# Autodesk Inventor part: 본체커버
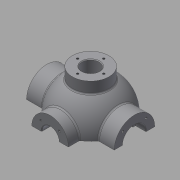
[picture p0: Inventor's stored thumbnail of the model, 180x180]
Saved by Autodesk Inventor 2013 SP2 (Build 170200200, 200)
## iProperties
Created: 2015-12
Part Number: 본체커버
Material: 일반
Document SubType Name: Modeling
Designer: mduedu
Density: 1 g/cm^3
Mass: 574.351 g
Surface Area: 450.515 cm^2
Volume: 211.938 cm^3
Author: mduedu
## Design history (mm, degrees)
sketch "스케치1"
  geometry: L1 (-53, 0)-(53, 0); A1 r 53 centre (0, 0) between (53, 0) and (-53, 0); 2 further points
  constraints: 2 coincident, 2 end point, 2 point on circle, 1 centre point, 1 horizontal, 1 midpoint
  dimensions: "d0" = 53 radius of A1
revolve "회전1" sketch "스케치1" stored, may be unused: angle "d2" = 90 deg
feature "쉘1" dims "d11" = 10
node "작업 평면1"
sketch "스케치2"
  geometry: C1 r 31 at (0, 0); 1 further point
  constraints: 1 centre point, 1 coincident
  dimensions: "d4" = 62 diameter of C1
extrude "돌출1" join sketch "스케치2" stored distance "d5" = 10; taper "d6" = 0 deg
node "작업 평면2"
sketch "스케치3"
  geometry: C1 r 28 at (0, 0); 1 further point
  constraints: 1 centre point, 1 coincident
  dimensions: "d8" = 56 diameter of C1
extrude "돌출2" join sketch "스케치3" stored distance "d9" = 10; taper "d10" = 0 deg
hole "구멍1" diameter "d14" = 35; stored, may be unused: countersink angle "d18" = 90 deg, drill point angle "d20" = 0 deg; dims "d12" = 10, "d13" = 10, "d15" = 6, "d16" = 4, "d17" = 2, "d19" = 16
hole "구멍2" diameter "d23" = 27; stored, may be unused: countersink angle "d27" = 90 deg, drill point angle "d29" = 0 deg; dims "d21" = 10, "d22" = 10, "d24" = 6, "d25" = 4, "d26" = 2, "d28" = 16
fillet "모깎기1" dims "d30" = 0.3
hole "구멍3" diameter "d33" = 26; stored, may be unused: countersink angle "d37" = 90 deg, drill point angle "d39" = 0 deg; dims "d31" = 10, "d32" = 10, "d34" = 6, "d35" = 4, "d36" = 2, "d38" = 16
chamfer "모따기1" distance "d40" = 1; stored, may be unused: second distance "d41" = 2, angle "d42" = 45 deg
sketch "스케치4"
  geometry: L1 (0, 0)-(0, -25); L2 (0, 0)-(-17.678, -17.678); A1 r 25 centre (0, 0) between (-17.678, -17.678) and (0, -25); 1 further point
  constraints: 4 end point, 2 point on circle, 1 centre point, 1 coincident, 1 vertical
  dimensions: "d43" = 50 diameter of A1; "d47" = 45 deg angle of L1 L2
hole "구멍4" sketch "스케치4" at (-17.678, -17.678) diameter "d49" = 3.242; stored, may be unused: countersink angle "d53" = 90 deg, drill point angle "d55" = 118 deg; dims "d50" = 11, "d51" = 4, "d52" = 2, "d54" = 13
sketch "스케치5"
  geometry: L1 (0, 0)-(0, -20); L2 (0, 0)-(-14.142, -14.142); A1 r 20 centre (0, 0) between (0, -20) and (-14.142, -14.142); 2 further points
  constraints: 4 end point, 2 coincident, 2 point on circle, 1 centre point, 1 vertical
  dimensions: "d59" = 40 diameter of A1; "d65" = 45 deg angle of L1 L2
hole "구멍5" sketch "스케치5" at (-14.142, -14.142) diameter "d67" = 3.242; stored, may be unused: countersink angle "d71" = 90 deg, drill point angle "d73" = 118 deg; dims "d68" = 8, "d69" = 4, "d70" = 2, "d72" = 10
node "작업 평면3"
sketch "스케치6"
  geometry: C1 r 65 at (0, 0); 1 further point
  constraints: 1 centre point, 1 coincident
  dimensions: "d78" = 130 diameter of C1
extrude "돌출3" join sketch "스케치6" distance "d80" = 10; taper "d81" = 0 deg
sketch "스케치7"
  geometry: C1 r 20 at (0, 0); 1 further point
  constraints: 1 centre point, 1 coincident
  dimensions: "d82" = 40 diameter of C1
extrude "돌출4" join sketch "스케치7" stored distance "d84" = 10; taper "d85" = 0 deg
sketch "스케치8"
  geometry: 2 further points
  constraints: 1 coincident
hole "구멍6" sketch "스케치8" at (0, 0) diameter "d86" = 20; stored, may be unused: countersink angle "d90" = 90 deg, drill point angle "d92" = 118 deg; dims "d87" = 7, "d88" = 40, "d89" = 5, "d91" = 10
fillet "모깎기2" dims "d93" = 0.3
sketch "스케치9"
  geometry: L1 (65, -75)-(-65, -75) reference; L2 (-45, -75)-(-38.245, -36.692); A1 r 53 centre (0, 0) between (42.988, 31) and (42.988, -31) reference; 1 further point
  constraints: 2 end point, 1 point on circle, 1 point on line
  dimensions: "d94" = 45 horizontal distance of L2.start point (0, 0); "d95" = 80 deg angle of L2 L1
feature "리브1" sketch "스케치9" dims "d96" = 1, "d97" = 8, "d98" = 0, "d99" = 0, "d100" = 1, "d101" = 1
sketch "스케치10"
  geometry: L1 (0, 0)-(0, -55); L2 (0, 0)-(-38.891, -38.891); A1 r 55 centre (0, 0) between (0, -55) and (-38.891, -38.891); 2 further points
  constraints: 4 end point, 2 coincident, 2 point on circle, 1 centre point, 1 vertical
  dimensions: "d105" = 110 diameter of A1; "d107" = 45 deg angle of L1 L2
hole "구멍7" sketch "스케치10" at (-38.891, -38.891) diameter "d109" = 10; stored, may be unused: countersink angle "d113" = 90 deg, drill point angle "d115" = 118 deg; dims "d110" = 7, "d111" = 40, "d112" = 5, "d114" = 10
fillet "모깎기3" dims "d120" = 3
fillet "모깎기4" dims "d121" = 3, "d122" = 3
fillet "모깎기5" dims "d123" = 3
fillet "모깎기6" dims "d124" = 3
sketch "스케치11"
  geometry: C1 r 5 at (-38.891, 38.891) reference; C2 r 5 at (38.891, 38.891) reference; C3 r 5 at (38.891, -38.891) reference; C4 r 5 at (-38.891, -38.891) reference; C5 r 20 at (0, 0) reference; C6 r 65 at (0, 0) reference; 1 further point
  constraints: 3 other
feature "엠보싱1" sketch "스케치11" dims "d125" = 0.5, "d126" = 0
sketch "스케치12"
  geometry: L1 (0, 100)-(0, -100); L2 (0, 100)-(-150, 100); L3 (-150, 100)-(-150, -100); L4 (-150, -100)-(0, -100); 2 further points
  constraints: 8 end point, 3 perpendicular, 1 coincident, 1 midpoint, 1 vertical
  dimensions: "d127" = 200 distance of L2.end L3.end; "d129" = 150 distance of L3.end L1.end
extrude "돌출5" cut sketch "스케치12" stored distance "d130" = 10; taper "d131" = 0 deg
sketch "스케치13"
  geometry: C1 r 7 at (0, -53); A1 r 53 centre (0, 0) between (-42.113, -32.179) and (42.113, -32.179) reference; 1 further point
  constraints: 1 centre point, 1 point on circle
  dimensions: "d132" = 14 diameter of C1
extrude "돌출6" join sketch "스케치13" distance "d133" = 5; taper "d134" = 0 deg
sketch "스케치14"
  geometry: C1 r 7 at (0, 0) reference; 1 further point
extrude "돌출7" cut sketch "스케치14" stored distance "d135" = 5; taper "d136" = 0 deg
sketch "스케치15"
  geometry: C1 r 2.25 at (0, 53); A1 r 7 centre (0, 53) between (6.965, 52.302) and (-6.965, 52.302) reference; 1 further point
  constraints: 1 centre point, 1 coincident
  dimensions: "d139" = 4.5 diameter of C1
extrude "돌출8" cut sketch "스케치15" stored distance "d141" = 5; taper "d142" = 0 deg
fillet "모깎기7" dims "d143" = 3
fillet "모깎기8" dims "d144" = 1
fillet "모깎기9" dims "d145" = 1
fillet "모깎기10" dims "d146" = 1
node "작업 평면4"
sketch "스케치16"
  geometry: C1 r 28 at (0, 0); 1 further point
  constraints: 1 centre point, 1 coincident
  dimensions: "d148" = 56 diameter of C1
extrude "돌출9" join sketch "스케치16" stored distance "d150" = 5; taper "d151" = 0 deg
hole "구멍8" diameter "d154" = 26; stored, may be unused: countersink angle "d158" = 90 deg, drill point angle "d160" = 118 deg; dims "d152" = 10, "d153" = 10, "d155" = 6, "d156" = 4, "d157" = 2, "d159" = 8
sketch "스케치17" dims "d161" = 40
  geometry: 3 further points
  constraints: 2 vertical alignment, 1 coincident, 2 other
hole "구멍9" sketch "스케치17" at (0, 20) diameter "d163" = 3.242; stored, may be unused: countersink angle "d167" = 90 deg, drill point angle "d169" = 118 deg; dims "d164" = 8, "d165" = 4, "d166" = 2, "d168" = 10
fillet "모깎기11" dims "d173" = 3
chamfer "모따기2" distance "d174" = 1; stored, may be unused: second distance "d175" = 2, angle "d176" = 45 deg
node "솔리드1"
mirror "대칭1"
mirror "대칭2"
pattern_circular "원형 패턴1" dims angle "d57" = 360 deg
mirror "대칭3"
pattern_circular "원형 패턴2" dims angle "d75" = 360 deg
pattern_circular "원형 패턴3" dims angle "d103" = 360 deg
pattern_circular "원형 패턴4" dims angle "d118" = 360 deg
pattern_circular "원형 패턴5" dims angle "d171" = 360 deg
node "투영된 루프1"
other parameters: "d3" = 67, "d7" = 62, "d77" = -85, "d147" = 62
